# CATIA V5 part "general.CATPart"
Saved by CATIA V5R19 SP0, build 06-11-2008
Part number: skl_general
Publications: "Plan.1", "Point.1", "Point.2", "Point.3", "Point.4", "Point.5", "Point.6", "Point.7", "Point.9", "Point.8", "Point.10", "Point.11", "Point.12", "Longueur.barre"
Bounding box of the stored display mesh (mm): x -500 to 500, y 270 to 580, z 0 to 0
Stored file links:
  C:\Users\Thibaud\Desktop\IFMA\thinkmotion\IAO\modele_catia\squelette\general.CATPart

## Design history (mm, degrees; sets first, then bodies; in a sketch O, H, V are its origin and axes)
Parameters
  Longueur.barre = 170 mm
Body1 (main body)
  Plane1: type Offset, Offset 0, RefPlane xy-plane
  Point1: (0, 0, 0)
  Point2 "Point.2": (0, 410, 0)
  Point3 "Point.3": (0, 580 {= 410mm+Longueur.barre}, 0)
  Point4: (110, 355, 0)
  Point5: (-110, 355, 0)
  Point6: (240, 330, 0)
  Point7: (-240, 330, 0)
  Point8: (215, 560, 0)
  Point9: (-215, 560, 0)
  Point10: (500, 270, 0)
  Point11: (-500, 270, 0)
  Point12 "Point.12": (-150, 560, 0)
